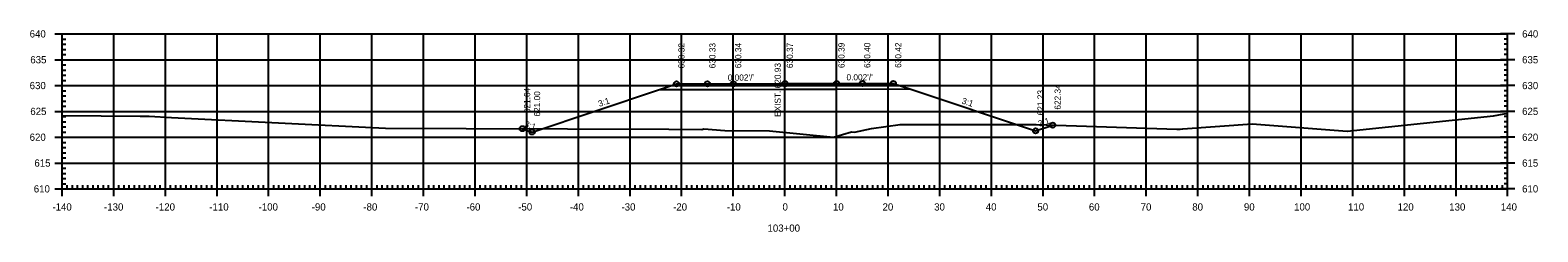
# Model space of a CAD drawing. Extents: x 1381471 to 1382703, y 370300 to 371487.
# Drawn here: x 1381476.5 to 1381768.6, y 370829.4 to 370868.4 of the extents above; entities that cross this region are included whole.
import ezdxf

# ---------------------------------------------------------------- set-up
doc = ezdxf.new("R2010")
doc.units = 0
for name, color, linetype in [('Level 18', 7, 'Continuous'), ('Level 2', 7, 'Continuous'), ('Level 20', 7, 'Continuous'), ('Level 22', 7, 'Continuous'), ('Level 26', 7, 'Continuous'), ('Level 4', 7, 'Continuous'), ('Level 41', 7, 'Continuous'), ('Level 42', 7, 'Continuous'), ('Level 5', 7, 'Continuous')]:
    doc.layers.add(name, color=color, linetype=linetype)

msp = doc.modelspace()

# ---------------------------------------------------------------- linework, layer by layer
at = {"layer": 'Level 18'}
msp.add_lwpolyline([(1381482.74, 370851.85), (1381497.87, 370851.75), (1381499.59, 370851.74), (1381503.9, 370851.52), (1381545.36, 370849.43), (1381561.02, 370849.37), (1381600.27, 370849.21), (1381606.66, 370849.19), (1381607.06, 370849.28), (1381611.1, 370848.99), (1381619.74, 370848.91), (1381632.15, 370847.66), (1381635.62, 370848.73), (1381636.24, 370848.67), (1381639.54, 370849.37), (1381645.09, 370850.14), (1381670.34, 370850.12), (1381671.42, 370850.12), (1381698.68, 370849.26), (1381699.28, 370849.25), (1381699.8, 370849.33), (1381713.27, 370850.3), (1381731.64, 370848.83), (1381731.69, 370848.83), (1381732.87, 370848.95), (1381760.01, 370851.84), (1381762.08, 370852.22), (1381762.74, 370852.29)], dxfattribs=at)
at = {"layer": 'Level 2'}
msp.add_lwpolyline([(1381598.47, 370856.91), (1381612.74, 370856.94), (1381622.74, 370856.97), (1381632.74, 370856.99), (1381646.97, 370857.02)], dxfattribs=at)
at = {"layer": 'Level 20'}
msp.add_lwpolyline([(1381571.85, 370849.33), (1381573.78, 370848.68), (1381598.47, 370856.91), (1381601.74, 370858), (1381607.74, 370858.01), (1381612.74, 370858.03), (1381622.74, 370858.05), (1381632.74, 370858.07), (1381637.74, 370858.08), (1381643.74, 370858.1), (1381646.97, 370857.02), (1381671.3, 370848.91), (1381674.62, 370850.02)], dxfattribs=at)
at = {"layer": 'Level 22'}
for p, q in [((1381482.74, 370867.68), (1381762.74, 370867.68)), ((1381482.74, 370837.68), (1381482.74, 370867.68)), ((1381492.74, 370837.68), (1381492.74, 370867.68)), ((1381502.74, 370837.68), (1381502.74, 370867.68)), ((1381512.74, 370837.68), (1381512.74, 370867.68)), ((1381522.74, 370837.68), (1381522.74, 370867.68)), ((1381532.74, 370837.68), (1381532.74, 370867.68)), ((1381542.74, 370837.68), (1381542.74, 370867.68)), ((1381552.74, 370837.68), (1381552.74, 370867.68)), ((1381562.74, 370837.68), (1381562.74, 370867.68)), ((1381572.74, 370837.68), (1381572.74, 370867.68)), ((1381582.74, 370837.68), (1381582.74, 370867.68)), ((1381592.74, 370837.68), (1381592.74, 370867.68)), ((1381602.74, 370837.68), (1381602.74, 370867.68)), ((1381612.74, 370837.68), (1381612.74, 370867.68)), ((1381622.74, 370837.68), (1381622.74, 370867.68)), ((1381632.74, 370837.68), (1381632.74, 370867.68)), ((1381642.74, 370837.68), (1381642.74, 370867.68)), ((1381652.74, 370837.68), (1381652.74, 370867.68)), ((1381662.74, 370837.68), (1381662.74, 370867.68)), ((1381672.74, 370837.68), (1381672.74, 370867.68)), ((1381682.74, 370837.68), (1381682.74, 370867.68)), ((1381692.74, 370837.68), (1381692.74, 370867.68)), ((1381702.74, 370837.68), (1381702.74, 370867.68)), ((1381712.74, 370837.68), (1381712.74, 370867.68)), ((1381722.74, 370837.68), (1381722.74, 370867.68)), ((1381732.74, 370837.68), (1381732.74, 370867.68)), ((1381742.74, 370837.68), (1381742.74, 370867.68)), ((1381752.74, 370837.68), (1381752.74, 370867.68)), ((1381762.74, 370837.68), (1381762.74, 370867.68)), ((1381482.74, 370862.68), (1381762.74, 370862.68)), ((1381482.74, 370857.68), (1381762.74, 370857.68)), ((1381482.74, 370852.68), (1381762.74, 370852.68)), ((1381482.74, 370847.68), (1381762.74, 370847.68)), ((1381482.74, 370842.68), (1381762.74, 370842.68)), ((1381482.74, 370837.68), (1381762.74, 370837.68))]:
    msp.add_line(p, q, dxfattribs=at)
at = {"layer": 'Level 26'}
msp.add_lwpolyline([(1381571.85, 370849.33), (1381573.78, 370848.68), (1381598.47, 370856.91), (1381601.74, 370858), (1381607.74, 370858.01), (1381612.74, 370858.03), (1381622.74, 370858.05), (1381632.74, 370858.07), (1381637.74, 370858.08), (1381643.74, 370858.1), (1381646.97, 370857.02), (1381671.3, 370848.91), (1381674.62, 370850.02)], dxfattribs=at)
for centre in [(1381601.74, 370858), (1381607.74, 370858.01), (1381612.74, 370858.03), (1381622.74, 370858.05), (1381632.74, 370858.07), (1381637.74, 370858.08), (1381643.74, 370858.1), (1381571.85, 370849.33), (1381573.78, 370848.68), (1381573.78, 370848.68), (1381671.3, 370848.91), (1381671.3, 370848.91), (1381674.62, 370850.02)]:
    msp.add_circle(centre, 0.5, dxfattribs=at)
at = {"layer": 'Level 4'}
for p, q in [((1381481.34, 370867.68), (1381484.14, 370867.68)), ((1381482.74, 370837.68), (1381482.74, 370867.68)), ((1381482.74, 370866.68), (1381483.44, 370866.68)), ((1381482.74, 370865.68), (1381483.44, 370865.68)), ((1381764.14, 370867.68), (1381761.34, 370867.68)), ((1381762.74, 370866.68), (1381762.04, 370866.68)), ((1381762.74, 370865.68), (1381762.04, 370865.68)), ((1381762.74, 370837.68), (1381762.74, 370867.68)), ((1381481.34, 370862.68), (1381484.14, 370862.68)), ((1381482.74, 370864.68), (1381483.44, 370864.68)), ((1381482.74, 370863.68), (1381483.44, 370863.68)), ((1381764.14, 370862.68), (1381761.34, 370862.68)), ((1381762.74, 370864.68), (1381762.04, 370864.68)), ((1381762.74, 370863.68), (1381762.04, 370863.68)), ((1381482.74, 370861.68), (1381483.44, 370861.68)), ((1381482.74, 370860.68), (1381483.44, 370860.68)), ((1381482.74, 370859.68), (1381483.44, 370859.68)), ((1381762.74, 370861.68), (1381762.04, 370861.68)), ((1381762.74, 370860.68), (1381762.04, 370860.68)), ((1381762.74, 370859.68), (1381762.04, 370859.68)), ((1381481.34, 370857.68), (1381484.14, 370857.68)), ((1381482.74, 370858.68), (1381483.44, 370858.68)), ((1381482.74, 370856.68), (1381483.44, 370856.68)), ((1381764.14, 370857.68), (1381761.34, 370857.68)), ((1381762.74, 370858.68), (1381762.04, 370858.68)), ((1381762.74, 370856.68), (1381762.04, 370856.68)), ((1381482.74, 370855.68), (1381483.44, 370855.68)), ((1381482.74, 370854.68), (1381483.44, 370854.68)), ((1381482.74, 370853.68), (1381483.44, 370853.68)), ((1381762.74, 370855.68), (1381762.04, 370855.68)), ((1381762.74, 370854.68), (1381762.04, 370854.68)), ((1381762.74, 370853.68), (1381762.04, 370853.68)), ((1381481.34, 370852.68), (1381484.14, 370852.68)), ((1381482.74, 370851.68), (1381483.44, 370851.68)), ((1381764.14, 370852.68), (1381761.34, 370852.68)), ((1381762.74, 370851.68), (1381762.04, 370851.68)), ((1381482.74, 370850.68), (1381483.44, 370850.68)), ((1381482.74, 370849.68), (1381483.44, 370849.68)), ((1381482.74, 370848.68), (1381483.44, 370848.68)), ((1381762.74, 370850.68), (1381762.04, 370850.68)), ((1381762.74, 370849.68), (1381762.04, 370849.68)), ((1381762.74, 370848.68), (1381762.04, 370848.68)), ((1381481.34, 370847.68), (1381484.14, 370847.68)), ((1381482.74, 370846.68), (1381483.44, 370846.68)), ((1381482.74, 370845.68), (1381483.44, 370845.68)), ((1381764.14, 370847.68), (1381761.34, 370847.68)), ((1381762.74, 370846.68), (1381762.04, 370846.68)), ((1381762.74, 370845.68), (1381762.04, 370845.68)), ((1381481.34, 370842.68), (1381484.14, 370842.68)), ((1381482.74, 370844.68), (1381483.44, 370844.68)), ((1381482.74, 370843.68), (1381483.44, 370843.68)), ((1381764.14, 370842.68), (1381761.34, 370842.68)), ((1381762.74, 370844.68), (1381762.04, 370844.68)), ((1381762.74, 370843.68), (1381762.04, 370843.68)), ((1381482.74, 370841.68), (1381483.44, 370841.68)), ((1381482.74, 370840.68), (1381483.44, 370840.68)), ((1381482.74, 370839.68), (1381483.44, 370839.68)), ((1381482.74, 370836.28), (1381482.74, 370839.08)), ((1381492.74, 370836.28), (1381492.74, 370839.08)), ((1381502.74, 370836.28), (1381502.74, 370839.08)), ((1381512.74, 370836.28), (1381512.74, 370839.08)), ((1381522.74, 370836.28), (1381522.74, 370839.08)), ((1381532.74, 370836.28), (1381532.74, 370839.08)), ((1381542.74, 370836.28), (1381542.74, 370839.08)), ((1381552.74, 370836.28), (1381552.74, 370839.08)), ((1381562.74, 370836.28), (1381562.74, 370839.08)), ((1381572.74, 370836.28), (1381572.74, 370839.08)), ((1381582.74, 370836.28), (1381582.74, 370839.08)), ((1381592.74, 370836.28), (1381592.74, 370839.08)), ((1381602.74, 370836.28), (1381602.74, 370839.08)), ((1381612.74, 370836.28), (1381612.74, 370839.08)), ((1381622.74, 370836.28), (1381622.74, 370839.08)), ((1381632.74, 370836.28), (1381632.74, 370839.08)), ((1381642.74, 370836.28), (1381642.74, 370839.08)), ((1381652.74, 370836.28), (1381652.74, 370839.08)), ((1381662.74, 370836.28), (1381662.74, 370839.08)), ((1381672.74, 370836.28), (1381672.74, 370839.08)), ((1381682.74, 370836.28), (1381682.74, 370839.08)), ((1381692.74, 370836.28), (1381692.74, 370839.08)), ((1381702.74, 370836.28), (1381702.74, 370839.08)), ((1381712.74, 370836.28), (1381712.74, 370839.08)), ((1381722.74, 370836.28), (1381722.74, 370839.08)), ((1381732.74, 370836.28), (1381732.74, 370839.08)), ((1381742.74, 370836.28), (1381742.74, 370839.08)), ((1381752.74, 370836.28), (1381752.74, 370839.08)), ((1381762.74, 370841.68), (1381762.04, 370841.68)), ((1381762.74, 370840.68), (1381762.04, 370840.68)), ((1381762.74, 370839.68), (1381762.04, 370839.68)), ((1381762.74, 370836.28), (1381762.74, 370839.08)), ((1381481.34, 370837.68), (1381484.14, 370837.68)), ((1381482.74, 370838.68), (1381483.44, 370838.68)), ((1381482.74, 370837.68), (1381762.74, 370837.68)), ((1381483.74, 370837.68), (1381483.74, 370838.38)), ((1381484.74, 370837.68), (1381484.74, 370838.38)), ((1381485.74, 370837.68), (1381485.74, 370838.38)), ((1381486.74, 370837.68), (1381486.74, 370838.38)), ((1381487.74, 370837.68), (1381487.74, 370838.38)), ((1381488.74, 370837.68), (1381488.74, 370838.38)), ((1381489.74, 370837.68), (1381489.74, 370838.38)), ((1381490.74, 370837.68), (1381490.74, 370838.38)), ((1381491.74, 370837.68), (1381491.74, 370838.38)), ((1381493.74, 370837.68), (1381493.74, 370838.38)), ((1381494.74, 370837.68), (1381494.74, 370838.38)), ((1381495.74, 370837.68), (1381495.74, 370838.38)), ((1381496.74, 370837.68), (1381496.74, 370838.38)), ((1381497.74, 370837.68), (1381497.74, 370838.38)), ((1381498.74, 370837.68), (1381498.74, 370838.38)), ((1381499.74, 370837.68), (1381499.74, 370838.38)), ((1381500.74, 370837.68), (1381500.74, 370838.38)), ((1381501.74, 370837.68), (1381501.74, 370838.38)), ((1381503.74, 370837.68), (1381503.74, 370838.38)), ((1381504.74, 370837.68), (1381504.74, 370838.38)), ((1381505.74, 370837.68), (1381505.74, 370838.38)), ((1381506.74, 370837.68), (1381506.74, 370838.38)), ((1381507.74, 370837.68), (1381507.74, 370838.38)), ((1381508.74, 370837.68), (1381508.74, 370838.38)), ((1381509.74, 370837.68), (1381509.74, 370838.38)), ((1381510.74, 370837.68), (1381510.74, 370838.38)), ((1381511.74, 370837.68), (1381511.74, 370838.38)), ((1381513.74, 370837.68), (1381513.74, 370838.38)), ((1381514.74, 370837.68), (1381514.74, 370838.38)), ((1381515.74, 370837.68), (1381515.74, 370838.38)), ((1381516.74, 370837.68), (1381516.74, 370838.38)), ((1381517.74, 370837.68), (1381517.74, 370838.38)), ((1381518.74, 370837.68), (1381518.74, 370838.38)), ((1381519.74, 370837.68), (1381519.74, 370838.38)), ((1381520.74, 370837.68), (1381520.74, 370838.38)), ((1381521.74, 370837.68), (1381521.74, 370838.38)), ((1381523.74, 370837.68), (1381523.74, 370838.38)), ((1381524.74, 370837.68), (1381524.74, 370838.38)), ((1381525.74, 370837.68), (1381525.74, 370838.38)), ((1381526.74, 370837.68), (1381526.74, 370838.38)), ((1381527.74, 370837.68), (1381527.74, 370838.38)), ((1381528.74, 370837.68), (1381528.74, 370838.38)), ((1381529.74, 370837.68), (1381529.74, 370838.38)), ((1381530.74, 370837.68), (1381530.74, 370838.38)), ((1381531.74, 370837.68), (1381531.74, 370838.38)), ((1381533.74, 370837.68), (1381533.74, 370838.38)), ((1381534.74, 370837.68), (1381534.74, 370838.38)), ((1381535.74, 370837.68), (1381535.74, 370838.38)), ((1381536.74, 370837.68), (1381536.74, 370838.38)), ((1381537.74, 370837.68), (1381537.74, 370838.38)), ((1381538.74, 370837.68), (1381538.74, 370838.38)), ((1381539.74, 370837.68), (1381539.74, 370838.38)), ((1381540.74, 370837.68), (1381540.74, 370838.38)), ((1381541.74, 370837.68), (1381541.74, 370838.38)), ((1381543.74, 370837.68), (1381543.74, 370838.38)), ((1381544.74, 370837.68), (1381544.74, 370838.38)), ((1381545.74, 370837.68), (1381545.74, 370838.38)), ((1381546.74, 370837.68), (1381546.74, 370838.38)), ((1381547.74, 370837.68), (1381547.74, 370838.38)), ((1381548.74, 370837.68), (1381548.74, 370838.38)), ((1381549.74, 370837.68), (1381549.74, 370838.38)), ((1381550.74, 370837.68), (1381550.74, 370838.38)), ((1381551.74, 370837.68), (1381551.74, 370838.38)), ((1381553.74, 370837.68), (1381553.74, 370838.38)), ((1381554.74, 370837.68), (1381554.74, 370838.38)), ((1381555.74, 370837.68), (1381555.74, 370838.38)), ((1381556.74, 370837.68), (1381556.74, 370838.38)), ((1381557.74, 370837.68), (1381557.74, 370838.38)), ((1381558.74, 370837.68), (1381558.74, 370838.38)), ((1381559.74, 370837.68), (1381559.74, 370838.38)), ((1381560.74, 370837.68), (1381560.74, 370838.38)), ((1381561.74, 370837.68), (1381561.74, 370838.38)), ((1381563.74, 370837.68), (1381563.74, 370838.38)), ((1381564.74, 370837.68), (1381564.74, 370838.38)), ((1381565.74, 370837.68), (1381565.74, 370838.38)), ((1381566.74, 370837.68), (1381566.74, 370838.38)), ((1381567.74, 370837.68), (1381567.74, 370838.38)), ((1381568.74, 370837.68), (1381568.74, 370838.38)), ((1381569.74, 370837.68), (1381569.74, 370838.38)), ((1381570.74, 370837.68), (1381570.74, 370838.38)), ((1381571.74, 370837.68), (1381571.74, 370838.38)), ((1381573.74, 370837.68), (1381573.74, 370838.38)), ((1381574.74, 370837.68), (1381574.74, 370838.38)), ((1381575.74, 370837.68), (1381575.74, 370838.38)), ((1381576.74, 370837.68), (1381576.74, 370838.38)), ((1381577.74, 370837.68), (1381577.74, 370838.38)), ((1381578.74, 370837.68), (1381578.74, 370838.38)), ((1381579.74, 370837.68), (1381579.74, 370838.38)), ((1381580.74, 370837.68), (1381580.74, 370838.38)), ((1381581.74, 370837.68), (1381581.74, 370838.38)), ((1381583.74, 370837.68), (1381583.74, 370838.38)), ((1381584.74, 370837.68), (1381584.74, 370838.38)), ((1381585.74, 370837.68), (1381585.74, 370838.38)), ((1381586.74, 370837.68), (1381586.74, 370838.38)), ((1381587.74, 370837.68), (1381587.74, 370838.38)), ((1381588.74, 370837.68), (1381588.74, 370838.38)), ((1381589.74, 370837.68), (1381589.74, 370838.38)), ((1381590.74, 370837.68), (1381590.74, 370838.38)), ((1381591.74, 370837.68), (1381591.74, 370838.38)), ((1381593.74, 370837.68), (1381593.74, 370838.38)), ((1381594.74, 370837.68), (1381594.74, 370838.38)), ((1381595.74, 370837.68), (1381595.74, 370838.38)), ((1381596.74, 370837.68), (1381596.74, 370838.38)), ((1381597.74, 370837.68), (1381597.74, 370838.38)), ((1381598.74, 370837.68), (1381598.74, 370838.38)), ((1381599.74, 370837.68), (1381599.74, 370838.38)), ((1381600.74, 370837.68), (1381600.74, 370838.38)), ((1381601.74, 370837.68), (1381601.74, 370838.38)), ((1381603.74, 370837.68), (1381603.74, 370838.38)), ((1381604.74, 370837.68), (1381604.74, 370838.38)), ((1381605.74, 370837.68), (1381605.74, 370838.38)), ((1381606.74, 370837.68), (1381606.74, 370838.38)), ((1381607.74, 370837.68), (1381607.74, 370838.38)), ((1381608.74, 370837.68), (1381608.74, 370838.38)), ((1381609.74, 370837.68), (1381609.74, 370838.38)), ((1381610.74, 370837.68), (1381610.74, 370838.38)), ((1381611.74, 370837.68), (1381611.74, 370838.38)), ((1381613.74, 370837.68), (1381613.74, 370838.38)), ((1381614.74, 370837.68), (1381614.74, 370838.38)), ((1381615.74, 370837.68), (1381615.74, 370838.38)), ((1381616.74, 370837.68), (1381616.74, 370838.38)), ((1381617.74, 370837.68), (1381617.74, 370838.38)), ((1381618.74, 370837.68), (1381618.74, 370838.38)), ((1381619.74, 370837.68), (1381619.74, 370838.38)), ((1381620.74, 370837.68), (1381620.74, 370838.38)), ((1381621.74, 370837.68), (1381621.74, 370838.38)), ((1381623.74, 370837.68), (1381623.74, 370838.38)), ((1381624.74, 370837.68), (1381624.74, 370838.38)), ((1381625.74, 370837.68), (1381625.74, 370838.38)), ((1381626.74, 370837.68), (1381626.74, 370838.38)), ((1381627.74, 370837.68), (1381627.74, 370838.38)), ((1381628.74, 370837.68), (1381628.74, 370838.38)), ((1381629.74, 370837.68), (1381629.74, 370838.38)), ((1381630.74, 370837.68), (1381630.74, 370838.38)), ((1381631.74, 370837.68), (1381631.74, 370838.38)), ((1381633.74, 370837.68), (1381633.74, 370838.38)), ((1381634.74, 370837.68), (1381634.74, 370838.38)), ((1381635.74, 370837.68), (1381635.74, 370838.38)), ((1381636.74, 370837.68), (1381636.74, 370838.38)), ((1381637.74, 370837.68), (1381637.74, 370838.38)), ((1381638.74, 370837.68), (1381638.74, 370838.38)), ((1381639.74, 370837.68), (1381639.74, 370838.38)), ((1381640.74, 370837.68), (1381640.74, 370838.38)), ((1381641.74, 370837.68), (1381641.74, 370838.38)), ((1381643.74, 370837.68), (1381643.74, 370838.38)), ((1381644.74, 370837.68), (1381644.74, 370838.38)), ((1381645.74, 370837.68), (1381645.74, 370838.38)), ((1381646.74, 370837.68), (1381646.74, 370838.38)), ((1381647.74, 370837.68), (1381647.74, 370838.38)), ((1381648.74, 370837.68), (1381648.74, 370838.38)), ((1381649.74, 370837.68), (1381649.74, 370838.38)), ((1381650.74, 370837.68), (1381650.74, 370838.38)), ((1381651.74, 370837.68), (1381651.74, 370838.38)), ((1381653.74, 370837.68), (1381653.74, 370838.38)), ((1381654.74, 370837.68), (1381654.74, 370838.38)), ((1381655.74, 370837.68), (1381655.74, 370838.38)), ((1381656.74, 370837.68), (1381656.74, 370838.38)), ((1381657.74, 370837.68), (1381657.74, 370838.38)), ((1381658.74, 370837.68), (1381658.74, 370838.38)), ((1381659.74, 370837.68), (1381659.74, 370838.38)), ((1381660.74, 370837.68), (1381660.74, 370838.38)), ((1381661.74, 370837.68), (1381661.74, 370838.38)), ((1381663.74, 370837.68), (1381663.74, 370838.38)), ((1381664.74, 370837.68), (1381664.74, 370838.38)), ((1381665.74, 370837.68), (1381665.74, 370838.38)), ((1381666.74, 370837.68), (1381666.74, 370838.38)), ((1381667.74, 370837.68), (1381667.74, 370838.38)), ((1381668.74, 370837.68), (1381668.74, 370838.38)), ((1381669.74, 370837.68), (1381669.74, 370838.38)), ((1381670.74, 370837.68), (1381670.74, 370838.38)), ((1381671.74, 370837.68), (1381671.74, 370838.38)), ((1381673.74, 370837.68), (1381673.74, 370838.38)), ((1381674.74, 370837.68), (1381674.74, 370838.38)), ((1381675.74, 370837.68), (1381675.74, 370838.38)), ((1381676.74, 370837.68), (1381676.74, 370838.38)), ((1381677.74, 370837.68), (1381677.74, 370838.38)), ((1381678.74, 370837.68), (1381678.74, 370838.38)), ((1381679.74, 370837.68), (1381679.74, 370838.38)), ((1381680.74, 370837.68), (1381680.74, 370838.38)), ((1381681.74, 370837.68), (1381681.74, 370838.38)), ((1381683.74, 370837.68), (1381683.74, 370838.38)), ((1381684.74, 370837.68), (1381684.74, 370838.38)), ((1381685.74, 370837.68), (1381685.74, 370838.38)), ((1381686.74, 370837.68), (1381686.74, 370838.38)), ((1381687.74, 370837.68), (1381687.74, 370838.38)), ((1381688.74, 370837.68), (1381688.74, 370838.38)), ((1381689.74, 370837.68), (1381689.74, 370838.38)), ((1381690.74, 370837.68), (1381690.74, 370838.38)), ((1381691.74, 370837.68), (1381691.74, 370838.38)), ((1381693.74, 370837.68), (1381693.74, 370838.38)), ((1381694.74, 370837.68), (1381694.74, 370838.38)), ((1381695.74, 370837.68), (1381695.74, 370838.38)), ((1381696.74, 370837.68), (1381696.74, 370838.38)), ((1381697.74, 370837.68), (1381697.74, 370838.38)), ((1381698.74, 370837.68), (1381698.74, 370838.38)), ((1381699.74, 370837.68), (1381699.74, 370838.38)), ((1381700.74, 370837.68), (1381700.74, 370838.38)), ((1381701.74, 370837.68), (1381701.74, 370838.38)), ((1381703.74, 370837.68), (1381703.74, 370838.38)), ((1381704.74, 370837.68), (1381704.74, 370838.38)), ((1381705.74, 370837.68), (1381705.74, 370838.38)), ((1381706.74, 370837.68), (1381706.74, 370838.38)), ((1381707.74, 370837.68), (1381707.74, 370838.38)), ((1381708.74, 370837.68), (1381708.74, 370838.38)), ((1381709.74, 370837.68), (1381709.74, 370838.38)), ((1381710.74, 370837.68), (1381710.74, 370838.38)), ((1381711.74, 370837.68), (1381711.74, 370838.38)), ((1381713.74, 370837.68), (1381713.74, 370838.38)), ((1381714.74, 370837.68), (1381714.74, 370838.38)), ((1381715.74, 370837.68), (1381715.74, 370838.38)), ((1381716.74, 370837.68), (1381716.74, 370838.38)), ((1381717.74, 370837.68), (1381717.74, 370838.38)), ((1381718.74, 370837.68), (1381718.74, 370838.38)), ((1381719.74, 370837.68), (1381719.74, 370838.38)), ((1381720.74, 370837.68), (1381720.74, 370838.38)), ((1381721.74, 370837.68), (1381721.74, 370838.38)), ((1381723.74, 370837.68), (1381723.74, 370838.38)), ((1381724.74, 370837.68), (1381724.74, 370838.38)), ((1381725.74, 370837.68), (1381725.74, 370838.38)), ((1381726.74, 370837.68), (1381726.74, 370838.38)), ((1381727.74, 370837.68), (1381727.74, 370838.38)), ((1381728.74, 370837.68), (1381728.74, 370838.38)), ((1381729.74, 370837.68), (1381729.74, 370838.38)), ((1381730.74, 370837.68), (1381730.74, 370838.38)), ((1381731.74, 370837.68), (1381731.74, 370838.38)), ((1381733.74, 370837.68), (1381733.74, 370838.38)), ((1381734.74, 370837.68), (1381734.74, 370838.38)), ((1381735.74, 370837.68), (1381735.74, 370838.38)), ((1381736.74, 370837.68), (1381736.74, 370838.38)), ((1381737.74, 370837.68), (1381737.74, 370838.38)), ((1381738.74, 370837.68), (1381738.74, 370838.38)), ((1381739.74, 370837.68), (1381739.74, 370838.38)), ((1381740.74, 370837.68), (1381740.74, 370838.38)), ((1381741.74, 370837.68), (1381741.74, 370838.38)), ((1381743.74, 370837.68), (1381743.74, 370838.38)), ((1381744.74, 370837.68), (1381744.74, 370838.38)), ((1381745.74, 370837.68), (1381745.74, 370838.38)), ((1381746.74, 370837.68), (1381746.74, 370838.38)), ((1381747.74, 370837.68), (1381747.74, 370838.38)), ((1381748.74, 370837.68), (1381748.74, 370838.38)), ((1381749.74, 370837.68), (1381749.74, 370838.38)), ((1381750.74, 370837.68), (1381750.74, 370838.38)), ((1381751.74, 370837.68), (1381751.74, 370838.38)), ((1381753.74, 370837.68), (1381753.74, 370838.38)), ((1381754.74, 370837.68), (1381754.74, 370838.38)), ((1381755.74, 370837.68), (1381755.74, 370838.38)), ((1381756.74, 370837.68), (1381756.74, 370838.38)), ((1381757.74, 370837.68), (1381757.74, 370838.38)), ((1381758.74, 370837.68), (1381758.74, 370838.38)), ((1381759.74, 370837.68), (1381759.74, 370838.38)), ((1381760.74, 370837.68), (1381760.74, 370838.38)), ((1381764.14, 370837.68), (1381761.34, 370837.68)), ((1381761.74, 370837.68), (1381761.74, 370838.38)), ((1381762.74, 370838.68), (1381762.04, 370838.68))]:
    msp.add_line(p, q, dxfattribs=at)

# ---------------------------------------------------------------- texts
at = {"layer": 'Level 41'}
for s, p in [('630.32', (1381603.29, 370861)), ('630.33', (1381609.29, 370861.01)), ('630.34', (1381614.29, 370861.03)), ('630.37', (1381624.29, 370861.05)), ('630.39', (1381634.29, 370861.07)), ('630.40', (1381639.29, 370861.08)), ('630.42', (1381645.29, 370861.1)), ('EXIST. 620.93', (1381621.94, 370851.61)), ('621.64', (1381573.4, 370852.33)), ('621.23', (1381672.85, 370851.91)), ('622.34', (1381676.17, 370853.02)), ('621.00', (1381575.33, 370851.68))]:
    msp.add_text(s, height=1.2, rotation=90, dxfattribs=at).set_placement(p)
at = {"layer": 'Level 42'}
for s, rotation, p in [("0.002'/'", 0.1364, (1381611.67, 370858.62)), ("0.002'/'", 0.1365, (1381634.67, 370858.68)), ('3:1', 18.4349, (1381586.81, 370853.55)), ('3:1', 341.5651, (1381656.89, 370854.24)), ('3:1', 341.5651, (1381572.18, 370849.74)), ('3:1', 18.4349, (1381672.02, 370849.68))]:
    msp.add_text(s, height=1.2, rotation=rotation, dxfattribs=at).set_placement(p)
at = {"layer": 'Level 5'}
for s, p in [('640', (1381476.44, 370866.98)), ('640', (1381765.54, 370866.98)), ('635', (1381476.57, 370861.98)), ('635', (1381765.54, 370861.98)), ('630', (1381476.44, 370856.98)), ('630', (1381765.54, 370856.98)), ('625', (1381476.57, 370851.98)), ('625', (1381765.54, 370851.98)), ('620', (1381476.44, 370846.98)), ('620', (1381765.54, 370846.98)), ('615', (1381477.36, 370841.98)), ('615', (1381765.54, 370841.98)), ('610', (1381477.24, 370836.98)), ('610', (1381765.54, 370836.98)), ('-140', (1381480.85, 370833.48)), ('-130', (1381490.85, 370833.48)), ('-120', (1381500.85, 370833.48)), ('-110', (1381511.24, 370833.48)), ('-100', (1381520.79, 370833.48)), ('-90', (1381531.08, 370833.48)), ('-80', (1381541.08, 370833.48)), ('-70', (1381551.08, 370833.48)), ('-60', (1381561.05, 370833.48)), ('-50', (1381571.08, 370833.48)), ('-40', (1381581.08, 370833.48)), ('-30', (1381591.08, 370833.48)), ('-20', (1381601.08, 370833.48)), ('-10', (1381611.48, 370833.48)), ('0', (1381622.28, 370833.48)), ('10', (1381632.05, 370833.48)), ('20', (1381641.65, 370833.48)), ('30', (1381651.65, 370833.48)), ('40', (1381661.65, 370833.48)), ('50', (1381671.65, 370833.48)), ('60', (1381681.62, 370833.48)), ('70', (1381691.65, 370833.48)), ('80', (1381701.65, 370833.48)), ('90', (1381711.65, 370833.48)), ('100', (1381721.37, 370833.48)), ('110', (1381731.82, 370833.48)), ('120', (1381741.42, 370833.48)), ('130', (1381751.42, 370833.48)), ('140', (1381761.42, 370833.48)), ('103+00', (1381619.37, 370829.38))]:
    msp.add_text(s, height=1.4, dxfattribs=at).set_placement(p)

doc.saveas('drawing.dxf')
